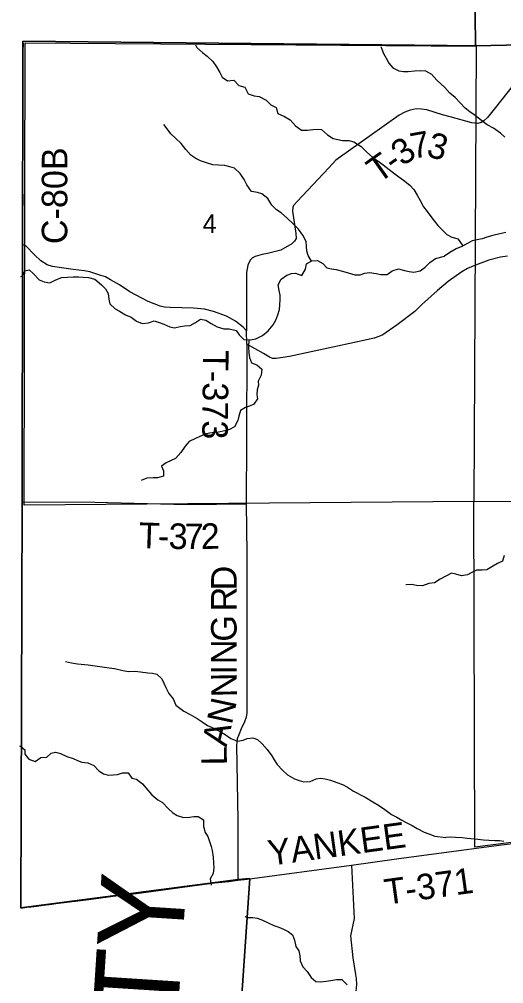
# Model space of a CAD drawing. Extents: x 1759416 to 2214760, y 252598 to 1116833.
# Drawn here: x 1928770 to 1934454, y 917809 to 929140 of the extents above; entities that cross this region are included whole.
import ezdxf

# ---------------------------------------------------------------- set-up
doc = ezdxf.new("R2010")
doc.units = 0
for name, color, linetype in [('GM_X_Adjacent_County', 7, 'Continuous'), ('GM_X_Adjacent_County_Text', 7, 'Continuous'), ('GM_X_County', 7, 'Continuous'), ('GM_X_County_Road', 7, 'Continuous'), ('GM_X_County_Road_Text', 7, 'Continuous'), ('GM_X_Minor_River', 7, 'Continuous'), ('GM_X_Section', 7, 'Continuous'), ('GM_X_Section_Text', 7, 'Continuous'), ('GM_X_Township', 7, 'Continuous'), ('GM_X_Township_Road', 7, 'Continuous'), ('GM_X_Township_Road_Text', 7, 'Continuous')]:
    doc.layers.add(name, color=color, linetype=linetype)

msp = doc.modelspace()

# ---------------------------------------------------------------- linework, layer by layer
at = {"layer": 'GM_X_Adjacent_County'}
for points in [[(1934067, 942157), (1934195, 936859), (1934202, 936590), (1934187, 936214), (1934165, 936177), (1934141, 936112), (1934134, 936040), (1934113, 935746), (1934115, 935394), (1934114, 935137), (1934107, 931513), (1934121, 929197), (1934122, 928828), (1933789, 928831), (1928810, 928882), (1928810, 928443), (1928806, 926508), (1928802, 923466), (1928787, 918701), (1931337, 919032), (1931473, 919044), (1931168, 914595)], [(1959742, 928940), (1957476, 928914), (1955313, 928900), (1953542, 928878), (1952146, 928858), (1951568, 928828), (1949992, 928829), (1949281, 928821), (1944689, 928838), (1941462, 928831), (1934664, 928840), (1934122, 928828), (1934121, 929197), (1934107, 931513), (1934114, 935137), (1934115, 935394), (1934113, 935746), (1934134, 936040), (1934141, 936112), (1934165, 936177), (1934187, 936214), (1934202, 936590), (1934195, 936859), (1934067, 942157)]]:
    msp.add_lwpolyline(points, dxfattribs=at)
at = {"layer": 'GM_X_County'}
msp.add_lwpolyline([(1931168, 914595), (1931473, 919044), (1931337, 919032), (1928787, 918701), (1928802, 923466), (1928806, 926508), (1928810, 928443), (1928810, 928882), (1933789, 928831), (1934122, 928828), (1934664, 928840), (1941462, 928831), (1944689, 928838), (1949281, 928821), (1949992, 928829), (1951568, 928828), (1952146, 928858), (1953542, 928878), (1955313, 928900), (1957476, 928914), (1959742, 928940)], dxfattribs=at)
at = {"layer": 'GM_X_County_Road'}
for points in [[(1928807, 926493), (1928809, 926621), (1928809, 926752), (1928812, 926899), (1928813, 926997), (1928812, 927177), (1928812, 927324), (1928811, 927487), (1928811, 927749), (1928813, 927847), (1928813, 928059), (1928812, 928190), (1928814, 928353), (1928815, 928468), (1928815, 928598), (1928816, 928761), (1928817, 928861)], [(1934500, 926357), (1934416, 926343), (1934280, 926308), (1934124, 926251), (1934030, 926211), (1933962, 926173), (1933803, 926060), (1933678, 925955), (1933495, 925787), (1933413, 925706), (1933203, 925548), (1933037, 925431), (1932989, 925411), (1932935, 925395), (1932704, 925343), (1931940, 925177), (1931784, 925155), (1931740, 925156), (1931704, 925170), (1931634, 925214), (1931440, 925324), (1931436, 925478), (1931398, 925521), (1931306, 925591), (1931202, 925650), (1931048, 925708), (1930942, 925732), (1930812, 925746), (1930538, 925753), (1930474, 925757), (1930422, 925769), (1930282, 925825), (1930068, 925939), (1929946, 926021), (1929838, 926079), (1929780, 926115), (1929726, 926131), (1929596, 926171), (1929534, 926184), (1929402, 926200), (1929265, 926218), (1929160, 926234), (1929097, 926255), (1929024, 926300), (1928949, 926372), (1928845, 926477), (1928807, 926493)]]:
    msp.add_lwpolyline(points, dxfattribs=at)
at = {"layer": 'GM_X_Minor_River'}
for points in [[(1930839, 928840), (1930852, 928807), (1930924, 928745), (1930976, 928705), (1931039, 928644), (1931083, 928580), (1931121, 928515), (1931150, 928459), (1931214, 928415), (1931286, 928426), (1931346, 928362), (1931416, 928343), (1931455, 928265), (1931527, 928241), (1931585, 928232), (1931665, 928188), (1931723, 928133), (1931784, 928103), (1931802, 928033), (1931880, 927996), (1931950, 927960), (1932011, 927889), (1932081, 927837), (1932153, 927836), (1932215, 927844), (1932265, 927850), (1932317, 927844), (1932387, 927781), (1932452, 927741), (1932508, 927726), (1932564, 927716), (1932636, 927714), (1932694, 927701), (1932780, 927647), (1932844, 927582), (1932919, 927516), (1932977, 927477), (1933041, 927429), (1933109, 927374), (1933160, 927334), (1933222, 927288), (1933280, 927249), (1933352, 927191), (1933401, 927140), (1933439, 927074), (1933473, 927010), (1933512, 926937), (1933554, 926883), (1933598, 926823), (1933639, 926772), (1933681, 926718), (1933790, 926607)], [(1933014, 928819), (1933022, 928790), (1933044, 928738), (1933073, 928682), (1933107, 928623), (1933151, 928569), (1933225, 928536), (1933277, 928528), (1933331, 928528), (1933409, 928535), (1933483, 928537), (1933537, 928533), (1933606, 928494), (1933668, 928426), (1933765, 928337)], [(1934469, 927754), (1934415, 927800), (1934333, 927860), (1934261, 927900), (1934195, 927952), (1934107, 928016), (1934055, 928051), (1934003, 928097), (1933945, 928157), (1933885, 928219), (1933823, 928273), (1933765, 928337)], [(1932198, 926299), (1932161, 926363), (1932145, 926415), (1932138, 926474), (1932134, 926528), (1932096, 926602), (1932047, 926673), (1931981, 926739), (1931916, 926801), (1931844, 926866), (1931788, 926902), (1931732, 926957), (1931687, 927033), (1931615, 927088), (1931563, 927104), (1931493, 927116), (1931440, 927193), (1931410, 927257), (1931360, 927326), (1931293, 927390), (1931241, 927408), (1931181, 927421), (1931109, 927425), (1931039, 927431), (1930977, 927448), (1930897, 927476), (1930841, 927505), (1930784, 927545), (1930724, 927611), (1930670, 927680), (1930601, 927744), (1930549, 927795), (1930505, 927853), (1930465, 927905)], [(1934479, 926635), (1934407, 926619), (1934325, 926600), (1934257, 926580), (1934200, 926560), (1934142, 926550), (1934082, 926538), (1934030, 926506), (1933964, 926470), (1933896, 926442), (1933822, 926398), (1933758, 926356)], [(1933977, 926477), (1933922, 926558), (1933850, 926575), (1933790, 926607)], [(1928787, 926118), (1928808, 926126), (1928836, 926184), (1928886, 926196), (1928938, 926148), (1929004, 926077), (1929060, 926055), (1929126, 926042), (1929192, 926074), (1929264, 926106), (1929334, 926109), (1929400, 926113), (1929466, 926113), (1929520, 926110), (1929582, 926104), (1929654, 926086), (1929733, 926021), (1929781, 925971), (1929811, 925917), (1929819, 925852), (1929830, 925798), (1929894, 925738), (1929946, 925709), (1930014, 925667), (1930081, 925641), (1930145, 925592), (1930213, 925564), (1930287, 925573), (1930353, 925597), (1930409, 925579), (1930465, 925556), (1930537, 925526), (1930591, 925516), (1930657, 925531), (1930709, 925539), (1930773, 925541), (1930839, 925576), (1930897, 925618), (1930959, 925606), (1931023, 925565), (1931091, 925527), (1931169, 925501), (1931233, 925504), (1931314, 925484), (1931350, 925433), (1931404, 925377), (1931484, 925375), (1931546, 925386), (1931624, 925426), (1931688, 925480), (1931747, 925550), (1931779, 925606), (1931803, 925666), (1931822, 925730), (1931826, 925782), (1931830, 925850), (1931829, 925900), (1931819, 925954), (1931809, 926018), (1931842, 926088), (1931908, 926132), (1931962, 926154), (1932012, 926156), (1932084, 926129), (1932130, 926203), (1932141, 926267), (1932201, 926301), (1932269, 926307), (1932333, 926270), (1932378, 926218), (1932434, 926207), (1932486, 926201), (1932564, 926181), (1932630, 926160), (1932708, 926136), (1932768, 926136), (1932824, 926155), (1932878, 926165), (1932958, 926151), (1933012, 926140), (1933088, 926142), (1933146, 926184), (1933218, 926207), (1933290, 926187), (1933346, 926177), (1933398, 926170), (1933472, 926184), (1933532, 926228), (1933589, 926282), (1933655, 926329), (1933758, 926356)], [(1931463, 925375), (1931459, 925293), (1931465, 925222), (1931471, 925166), (1931496, 925102), (1931558, 925078), (1931616, 925029), (1931606, 924959), (1931571, 924889), (1931575, 924839), (1931559, 924785), (1931558, 924729), (1931564, 924679), (1931522, 924619), (1931472, 924595), (1931422, 924579), (1931365, 924543), (1931345, 924477), (1931335, 924425), (1931296, 924353), (1931238, 924320), (1931180, 924304), (1931106, 924290), (1931054, 924283), (1931002, 924277), (1930950, 924267), (1930888, 924239), (1930838, 924216), (1930762, 924178), (1930717, 924126), (1930665, 924050), (1930604, 923980), (1930552, 923954), (1930492, 923927), (1930440, 923891), (1930460, 923833), (1930463, 923773), (1930393, 923751), (1930339, 923751), (1930265, 923748), (1930199, 923720)], [(1934459, 922838), (1934441, 922774), (1934383, 922744), (1934313, 922706), (1934256, 922672), (1934200, 922666), (1934134, 922666), (1934080, 922638), (1934030, 922611)], [(1934030, 922611), (1933960, 922601), (1933892, 922622), (1933842, 922632), (1933708, 922561)], [(1933708, 922561), (1933642, 922519), (1933575, 922509), (1933503, 922483), (1933431, 922487), (1933371, 922499), (1933305, 922495)], [(1929310, 921596), (1929382, 921577), (1929454, 921565), (1929578, 921556), (1929633, 921548), (1929689, 921538), (1929741, 921532), (1929823, 921521), (1929885, 921511), (1929983, 921488), (1930051, 921478), (1930127, 921479), (1930193, 921471), (1930277, 921461), (1930331, 921456), (1930383, 921446), (1930441, 921390), (1930464, 921339), (1930490, 921287), (1930524, 921217), (1930575, 921154), (1930607, 921080), (1930699, 921011), (1930776, 920973), (1930858, 920926), (1930916, 920886), (1930978, 920842), (1931031, 920817), (1931119, 920777), (1931187, 920738), (1931253, 920690), (1931329, 920657), (1931395, 920669), (1931445, 920691), (1931511, 920696), (1931565, 920678), (1931618, 920628), (1931680, 920559), (1931734, 920487), (1931761, 920437), (1931795, 920386), (1931857, 920316), (1931918, 920263), (1931998, 920215), (1932052, 920195), (1932108, 920182), (1932182, 920186), (1932254, 920216), (1932306, 920223), (1932360, 920217), (1932422, 920201), (1932496, 920174), (1932562, 920148), (1932622, 920117), (1932691, 920071), (1932827, 920002), (1932919, 919946), (1932986, 919905), (1933060, 919857), (1933136, 919798), (1933198, 919766), (1933258, 919731), (1933309, 919701), (1933381, 919667), (1933437, 919634), (1933521, 919590), (1933577, 919569), (1933646, 919543), (1933774, 919527)], [(1928770, 920602), (1928784, 920599), (1928836, 920558), (1928836, 920504), (1928880, 920448), (1928955, 920421), (1929024, 920465), (1929092, 920471), (1929142, 920518), (1929196, 920530), (1929254, 920512), (1929328, 920479), (1929400, 920455), (1929453, 920433), (1929505, 920412), (1929575, 920402), (1929643, 920372), (1929703, 920311), (1929759, 920275), (1929815, 920258), (1929871, 920262), (1929923, 920266), (1929981, 920286), (1930047, 920285), (1930090, 920225), (1930144, 920213), (1930214, 920156), (1930278, 920082), (1930323, 920029), (1930397, 919969), (1930449, 919936), (1930516, 919868), (1930570, 919816), (1930624, 919783), (1930696, 919761), (1930766, 919766), (1930818, 919774), (1930870, 919774), (1930930, 919733), (1930931, 919655), (1930951, 919587), (1930981, 919537), (1931000, 919481), (1931020, 919422), (1931032, 919372), (1931045, 919294), (1931049, 919226), (1931051, 919170), (1931044, 919104), (1931008, 919040), (1931020, 918968)], [(1934457, 919479), (1934403, 919487), (1934351, 919489), (1934279, 919491), (1934217, 919497), (1934151, 919501), (1934024, 919515), (1933968, 919523), (1933890, 919527), (1933832, 919529), (1933774, 919527)], [(1931416, 918598), (1931455, 918588), (1931509, 918588), (1931561, 918580), (1931617, 918559), (1931689, 918523), (1931755, 918494), (1931815, 918472), (1931871, 918450), (1931925, 918423), (1931976, 918381), (1931998, 918319), (1932016, 918247), (1932049, 918196), (1932061, 918138), (1932067, 918078), (1932098, 918006), (1932148, 917951), (1932194, 917883), (1932251, 917834), (1932307, 917832), (1932369, 917840), (1932427, 917848), (1932492, 917857), (1932553, 917857), (1932617, 917796)]]:
    msp.add_lwpolyline(points, dxfattribs=at)
at = {"layer": 'GM_X_Section'}
for points in [[(1934130, 928823), (1934102, 923475), (1928826, 923432), (1928839, 928862)], [(1934102, 923475), (1939462, 923488), (1939486, 920110), (1938227, 919938), (1934116, 919412)]]:
    msp.add_lwpolyline(points, close=True, dxfattribs=at)
at = {"layer": 'GM_X_Township'}
msp.add_lwpolyline([(1931168, 914595), (1931473, 919044), (1931337, 919032), (1928787, 918701), (1928802, 923466), (1928806, 926508), (1928810, 928443), (1928810, 928882), (1933789, 928831), (1934122, 928828), (1934664, 928840), (1941462, 928831), (1944689, 928838)], dxfattribs=at)
at = {"layer": 'GM_X_Township_Road'}
for points in [[(1934580, 928384), (1934341, 928082), (1934265, 927984), (1934219, 927945), (1934189, 927927), (1934151, 927917), (1934079, 927925), (1933827, 927992), (1933735, 928016), (1933551, 928075), (1933491, 928085), (1933425, 928089), (1933355, 928071), (1933293, 928049), (1933229, 928015), (1932874, 927761), (1932538, 927522), (1932484, 927486), (1932401, 927396), (1932029, 926998), (1931988, 926950), (1931978, 926928), (1931974, 926886), (1932016, 926624), (1932018, 926566), (1932000, 926534), (1931968, 926503), (1931840, 926429), (1931790, 926415), (1931683, 926387), (1931619, 926377), (1931537, 926352), (1931503, 926332), (1931477, 926308), (1931451, 926250), (1931435, 926166), (1931436, 925478)], [(1931440, 925324), (1931436, 924210), (1931431, 923441), (1931440, 922866), (1931440, 921928), (1931439, 921060), (1931439, 920986), (1931433, 920942), (1931411, 920884), (1931375, 920802), (1931344, 920733), (1931328, 920685), (1931318, 920607), (1931333, 919733), (1931335, 919024)], [(1931431, 923441), (1930736, 923433), (1929655, 923464), (1928802, 923466)], [(1932667, 919203), (1933196, 919277), (1934397, 919435), (1935223, 919536)], [(1931443, 919037), (1932667, 919203)], [(1932667, 919203), (1932698, 918575), (1932656, 918373), (1932683, 918111), (1932713, 917915), (1932721, 917868), (1932725, 917800), (1932719, 917722), (1932680, 917195), (1932626, 916261), (1932573, 915400), (1932544, 914901), (1932501, 914333), (1932485, 914069), (1932490, 913838), (1932528, 913302), (1932583, 912747), (1932658, 912023), (1932762, 911042), (1932812, 910438), (1932832, 909536), (1932835, 909306)], [(1928786, 918696), (1928859, 918706), (1928908, 918712), (1928973, 918721), (1929054, 918732), (1929151, 918744), (1929199, 918750), (1929489, 918787), (1929586, 918799), (1929700, 918813), (1929814, 918828), (1929960, 918847), (1930139, 918870), (1930317, 918893), (1930545, 918924), (1930886, 918970), (1931065, 918992), (1931227, 919011), (1931335, 919024)], [(1931335, 919024), (1931443, 919037)]]:
    msp.add_lwpolyline(points, dxfattribs=at)

# ---------------------------------------------------------------- texts
at = {"layer": 'GM_X_Adjacent_County_Text'}
msp.add_text('MORROW COUNTY', height=1000, rotation=86.2876, dxfattribs=at).set_placement((1929932, 906690))
at = {"layer": 'GM_X_County_Road_Text'}
msp.add_text('C-80B', height=300, rotation=90, dxfattribs=at).set_placement((1929333, 926498))
at = {"layer": 'GM_X_Section_Text'}
msp.add_text('4', height=221, rotation=0, dxfattribs=at).set_placement((1930921, 926628))
at = {"layer": 'GM_X_Township_Road_Text'}
for s, rotation, p in [('7', 10.2546, (1933387, 927499)), ('3', 344.5829, (1933534, 927534)), ('3', 35.3096, (1933268, 927406)), ('T', 35.3603, (1932985, 927205)), ('-', 35.3553, (1933168, 927334)), ('T-373', 269.4386, (1930926, 925254)), ('T', 358.1912, (1930167, 922929)), ('3', 359.0732, (1930520, 922918)), ('7', 0.0726, (1930710, 922915)), ('2', 1.2997, (1930902, 922915)), ('-', 358.4231, (1930393, 922922)), ('D', 90, (1931320, 922430)), ('R', 90, (1931320, 922183)), ('G', 90, (1931320, 921827)), ('N', 90, (1931320, 921563)), ('I', 90, (1931320, 921440)), ('N', 91.1812, (1931325, 921177)), ('N', 77.8999, (1931263, 920844)), ('A', 76.7315, (1931201, 920580)), ('L', 90.6857, (1931206, 920375)), ('YANKEE', 7.8243, (1931708, 919193)), ('T-371', 7.8153, (1933075, 918736))]:
    msp.add_text(s, height=300, rotation=rotation, dxfattribs=at).set_placement(p)

doc.saveas('drawing.dxf')
